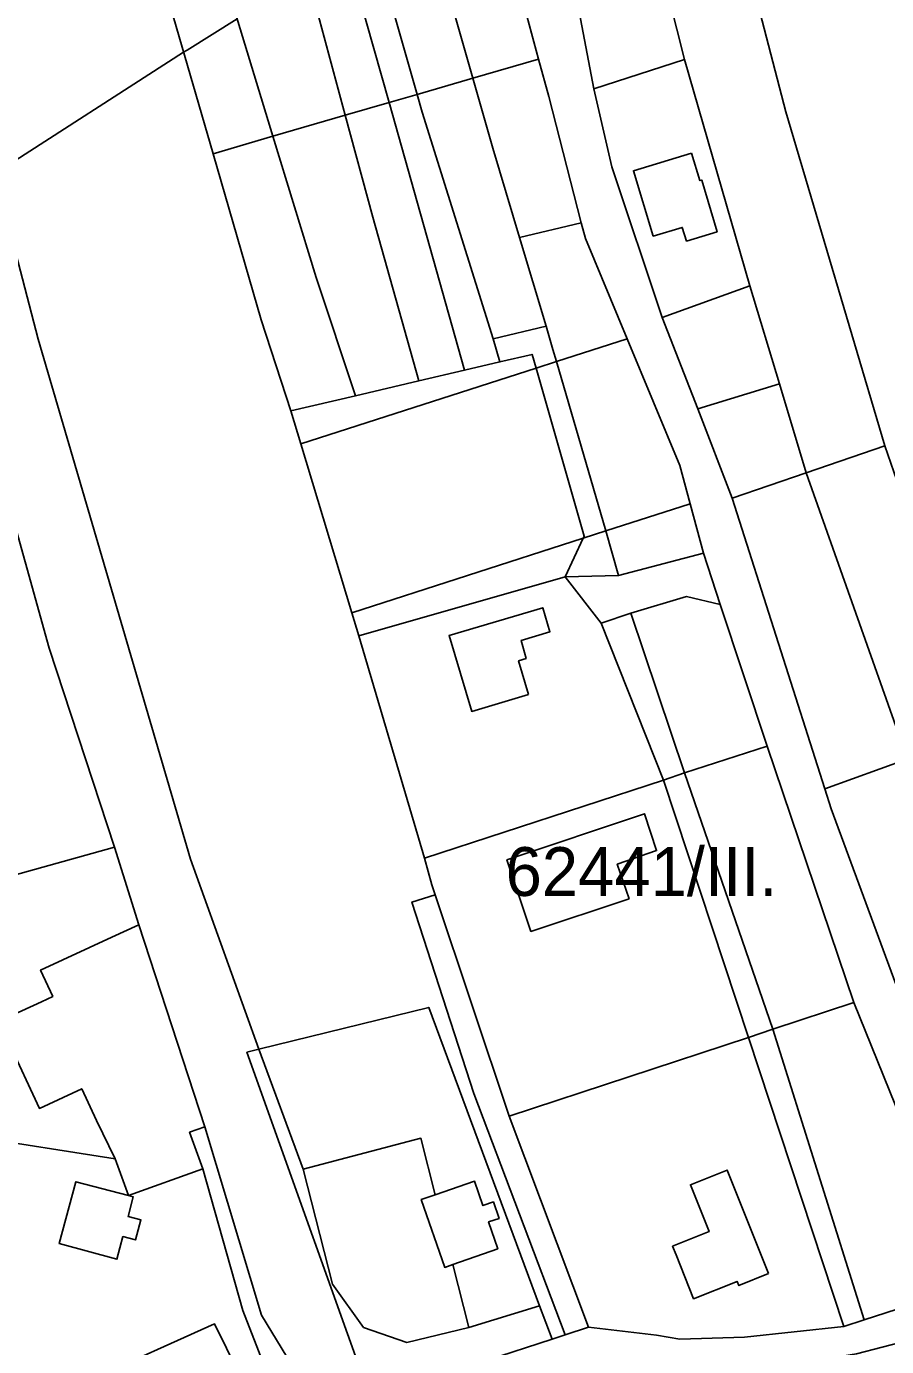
# Model space of a CAD drawing. Extents: x -502026 to -497664, y -1143484 to -1138019.
# Drawn here: x -498561.6 to -498420.5, y -1140148 to -1139931.4 of the extents above; entities that cross this region are included whole.
import ezdxf

# ---------------------------------------------------------------- set-up
doc = ezdxf.new("R2010")
doc.units = 0
for name, color, linetype in [('25', 7, 'Continuous'), ('37', 7, 'Continuous'), ('55', 7, 'Continuous'), ('62', 7, 'Continuous'), ('7', 7, 'Continuous')]:
    doc.layers.add(name, color=color, linetype=linetype)

msp = doc.modelspace()

# ---------------------------------------------------------------- linework, layer by layer
at = {"layer": '25'}
for points in [[(-498453.65, -1139936.81), (-498468.54, -1139941.63), (-498475.72, -1139903.67), (-498464.75, -1139892.81)], [(-498477.58, -1139936.75), (-498488.38, -1139939.89), (-498498.49, -1139904.41), (-498487.19, -1139901.13)], [(-498502.13, -1139943.88), (-498509.3, -1139945.96), (-498518.9, -1139910.34), (-498512.15, -1139908.38)], [(-498509.3, -1139945.96), (-498521.17, -1139949.4), (-498531.92, -1139914.12), (-498518.9, -1139910.34)], [(-498521.17, -1139949.4), (-498531.01, -1139952.26), (-498541.29, -1139916.84), (-498531.92, -1139914.12)], [(-498470.57, -1139963.59), (-498480.71, -1139966), (-498485.12, -1139951.34), (-498488.38, -1139939.89), (-498477.58, -1139936.75), (-498475.92, -1139942.9)], [(-498497.25, -1139989.53), (-498507.61, -1139991.96), (-498514.11, -1139972.59), (-498521.17, -1139949.4), (-498509.3, -1139945.96), (-498504.76, -1139962.67)], [(-498489.75, -1139987.77), (-498497.25, -1139989.53), (-498504.76, -1139962.67), (-498509.3, -1139945.96), (-498502.13, -1139943.88)], [(-498507.61, -1139991.96), (-498518.25, -1139994.45), (-498523.1, -1139979.49), (-498531.01, -1139952.26), (-498521.17, -1139949.4), (-498514.11, -1139972.59)], [(-498463.07, -1139982.62), (-498474.67, -1139986.36), (-498475.24, -1139984.39), (-498476.33, -1139980.54), (-498480.71, -1139966), (-498470.57, -1139963.59), (-498469.91, -1139966.15)], [(-498452.72, -1140009.7), (-498466.57, -1140014.16), (-498474.67, -1139986.36), (-498463.07, -1139982.62), (-498454.43, -1140003.42)], [(-498450.51, -1140017.8), (-498464.45, -1140021.44), (-498466.57, -1140014.16), (-498452.72, -1140009.7)]]:
    msp.add_lwpolyline(points, close=True, dxfattribs=at)
for points in [[(-498567.4, -1140071.66), (-498547.17, -1140066.02), (-498543.21, -1140078.75), (-498547.64, -1140080.8), (-498559.32, -1140086.21), (-498557.32, -1140090.52), (-498559.18, -1140091.38), (-498565.61, -1140094.35)], [(-498564.56, -1140097.96), (-498559.5, -1140108.89), (-498552.56, -1140105.68), (-498550.14, -1140110.9), (-498547.05, -1140117.17), (-498570.8, -1140113.45)]]:
    msp.add_lwpolyline(points, dxfattribs=at)
at = {"layer": '37'}
for points in [[(-498580.7, -1139904.91), (-498574.32, -1139926.66), (-498559.71, -1139982.7), (-498534.68, -1140067.99), (-498523.51, -1140099.19), (-498525.46, -1140099.67), (-498503.51, -1140161.05), (-498513.07, -1140159.27), (-498523.05, -1140142.79), (-498532.36, -1140111.9), (-498543.21, -1140078.75), (-498547.17, -1140066.02), (-498557.89, -1140033.39), (-498577.39, -1139963.52), (-498584.01, -1139942.13), (-498590.01, -1139920.48), (-498609.44, -1139845.64), (-498615.65, -1139814.41), (-498623.41, -1139785.38), (-498626.05, -1139772.41), (-498623.42, -1139762.03), (-498619.31, -1139757.84), (-498592.84, -1139833.58), (-498587.99, -1139880.06)], [(-498541.29, -1139916.84), (-498531.01, -1139952.26), (-498523.1, -1139979.49), (-498518.25, -1139994.45), (-498516.61, -1139999.88), (-498508.23, -1140027.57), (-498507.09, -1140031.35), (-498496.31, -1140067.84), (-498495.12, -1140072.22), (-498494.58, -1140073.83), (-498498.36, -1140075.04), (-498488.21, -1140106.42), (-498473.2, -1140146.05), (-498475.38, -1140146.76), (-498477.41, -1140141.29), (-498495.61, -1140092.32), (-498523.51, -1140099.19), (-498534.68, -1140067.99), (-498559.71, -1139982.7), (-498574.32, -1139926.66), (-498580.7, -1139904.91), (-498547.72, -1139894.69)], [(-498488.38, -1139939.89), (-498497.5, -1139942.53), (-498507.62, -1139907.06), (-498498.49, -1139904.41)], [(-498584.01, -1139942.13), (-498577.39, -1139963.52), (-498557.89, -1140033.39), (-498547.17, -1140066.02), (-498567.4, -1140071.66), (-498610.66, -1139931.23), (-498596.15, -1139928.3)], [(-498480.71, -1139966), (-498476.33, -1139980.54), (-498485.06, -1139982.65), (-498496.67, -1139945.43), (-498497.5, -1139942.53), (-498488.38, -1139939.89), (-498485.12, -1139951.34)], [(-498474.67, -1139986.36), (-498478, -1139987.43), (-498478.65, -1139985.18), (-498483.93, -1139986.41), (-498485.06, -1139982.65), (-498476.33, -1139980.54), (-498475.24, -1139984.39)], [(-498478, -1139987.43), (-498516.61, -1139999.88), (-498518.25, -1139994.45), (-498507.61, -1139991.96), (-498497.25, -1139989.53), (-498489.75, -1139987.77), (-498483.93, -1139986.41), (-498478.65, -1139985.18)], [(-498466.57, -1140014.16), (-498470.25, -1140015.35), (-498470.09, -1140015), (-498478, -1139987.43), (-498474.67, -1139986.36)], [(-498470.25, -1140015.35), (-498508.23, -1140027.57), (-498516.61, -1139999.88), (-498478, -1139987.43), (-498470.09, -1140015)], [(-498414.84, -1140017.25), (-498405.56, -1140044.31), (-498418.01, -1140048.78), (-498433.69, -1140004.63), (-498420.78, -1140000.2)], [(-498464.45, -1140021.44), (-498473.25, -1140021.69), (-498470.25, -1140015.35), (-498466.57, -1140014.16)], [(-498473.25, -1140021.69), (-498507.09, -1140031.35), (-498508.23, -1140027.57), (-498470.25, -1140015.35)], [(-498447.8, -1140026.22), (-498453.32, -1140024.92), (-498462.44, -1140027.62), (-498467.29, -1140029.26), (-498473.25, -1140021.69), (-498464.45, -1140021.44), (-498450.51, -1140017.8)], [(-498467.29, -1140029.26), (-498457.06, -1140055.04), (-498496.31, -1140067.84), (-498507.09, -1140031.35), (-498473.25, -1140021.69)], [(-498447.8, -1140026.22), (-498440.06, -1140049.48), (-498453.63, -1140053.81), (-498462.44, -1140027.62), (-498453.32, -1140024.92)], [(-498479.22, -1140040.97), (-498480.88, -1140035.47), (-498479.63, -1140035.09), (-498480.46, -1140032.1), (-498475.73, -1140030.7), (-498476.89, -1140026.75), (-498492.28, -1140031.32), (-498488.54, -1140043.77)], [(-498453.63, -1140053.81), (-498457.06, -1140055.04), (-498467.29, -1140029.26), (-498462.44, -1140027.62)], [(-498425.83, -1140091.5), (-498439.14, -1140095.88), (-498453.63, -1140053.81), (-498440.06, -1140049.48)], [(-498439.14, -1140095.88), (-498443.16, -1140097.25), (-498457.06, -1140055.04), (-498453.63, -1140053.81)], [(-498443.16, -1140097.25), (-498482.39, -1140110.14), (-498494.58, -1140073.83), (-498495.12, -1140072.22), (-498496.31, -1140067.84), (-498457.06, -1140055.04)], [(-498462.72, -1140074.51), (-498464.68, -1140068.83), (-498458.21, -1140066.6), (-498460.23, -1140060.56), (-498482.78, -1140068.12), (-498478.84, -1140079.86)], [(-498408.36, -1140134.77), (-498413.47, -1140140.15), (-498424.15, -1140143.6), (-498439.14, -1140095.88), (-498425.83, -1140091.5)], [(-498427.49, -1140144.66), (-498443.79, -1140146.41), (-498454.39, -1140146.74), (-498458.25, -1140146.09), (-498469.37, -1140144.8), (-498482.39, -1140110.14), (-498443.16, -1140097.25)], [(-498424.15, -1140143.6), (-498427.49, -1140144.66), (-498443.16, -1140097.25), (-498439.14, -1140095.88)], [(-498516.23, -1140118.88), (-498511.4, -1140137.73), (-498506.3, -1140144.84), (-498499.22, -1140147.29), (-498489.05, -1140144.84), (-498477.41, -1140141.29), (-498475.38, -1140146.76), (-498486.14, -1140150.27), (-498503.51, -1140161.05), (-498525.46, -1140099.67), (-498523.51, -1140099.19)], [(-498547.05, -1140117.17), (-498544.9, -1140123.19), (-498553.52, -1140120.93), (-498556.27, -1140131.07), (-498546.77, -1140133.65), (-498545.8, -1140129.93), (-498543.71, -1140130.48), (-498542.85, -1140127.18), (-498544.93, -1140126.63), (-498544.09, -1140123.4), (-498544.9, -1140123.19), (-498532.69, -1140118.83), (-498526.12, -1140142.06), (-498518.02, -1140162.88), (-498520.94, -1140164.17), (-498530.79, -1140144.21), (-498571.63, -1140162.6), (-498560.56, -1140182.88), (-498581.76, -1140187.79), (-498588.51, -1140166.89), (-498590.01, -1140162.02), (-498598.07, -1140136.66), (-498605.95, -1140115.74), (-498570.8, -1140113.45)], [(-498439.85, -1140136), (-498446.64, -1140119), (-498452.68, -1140121.42), (-498449.61, -1140129.11), (-498455.6, -1140131.51), (-498455.01, -1140132.92), (-498452.14, -1140140.13), (-498445, -1140137.27), (-498444.72, -1140137.97)], [(-498520.94, -1140164.17), (-498560.56, -1140182.88), (-498571.63, -1140162.6), (-498530.79, -1140144.21)]]:
    msp.add_lwpolyline(points, close=True, dxfattribs=at)
at = {"layer": '55'}
for points in [[(-498475.72, -1139903.67), (-498468.54, -1139941.63), (-498465.55, -1139954.43), (-498457.33, -1139979.14), (-498451.44, -1139994.1), (-498445.81, -1140008.75), (-498430.63, -1140056.46), (-498429.55, -1140059.73), (-498414.01, -1140101.85), (-498406.6, -1140113.23), (-498399.47, -1140125.86), (-498408.36, -1140134.77), (-498425.83, -1140091.5), (-498440.06, -1140049.48), (-498447.8, -1140026.22), (-498450.51, -1140017.8), (-498452.72, -1140009.7), (-498454.43, -1140003.42), (-498463.07, -1139982.62), (-498469.91, -1139966.15), (-498470.57, -1139963.59), (-498475.92, -1139942.9), (-498477.58, -1139936.75), (-498487.19, -1139901.13)], [(-498486.14, -1140150.27), (-498475.38, -1140146.76), (-498473.2, -1140146.05), (-498469.37, -1140144.8), (-498458.25, -1140146.09), (-498454.39, -1140146.74), (-498443.79, -1140146.41), (-498427.49, -1140144.66), (-498424.15, -1140143.6), (-498413.47, -1140140.15)], [(-498412.76, -1140145.86), (-498425.44, -1140149.16)]]:
    msp.add_lwpolyline(points, dxfattribs=at)
for points in [[(-498497.5, -1139942.53), (-498502.13, -1139943.88), (-498512.15, -1139908.38), (-498507.62, -1139907.06)], [(-498442.94, -1139973.93), (-498457.33, -1139979.14), (-498465.55, -1139954.43), (-498468.54, -1139941.63), (-498453.65, -1139936.81)], [(-498485.06, -1139982.65), (-498483.93, -1139986.41), (-498489.75, -1139987.77), (-498502.13, -1139943.88), (-498497.5, -1139942.53), (-498496.67, -1139945.43)], [(-498452.47, -1139952.17), (-498451.1, -1139956.68), (-498450.82, -1139956.59), (-498448.3, -1139965.07), (-498453.3, -1139966.6), (-498454.02, -1139964.35), (-498458.78, -1139965.77), (-498462.01, -1139955.06)], [(-498452.47, -1139952.17), (-498462.01, -1139955.06), (-498458.78, -1139965.77), (-498454.02, -1139964.35), (-498453.3, -1139966.6), (-498448.3, -1139965.07), (-498450.82, -1139956.59), (-498451.1, -1139956.68)], [(-498418.01, -1140048.78), (-498416.97, -1140051.55), (-498430.63, -1140056.46), (-498445.81, -1140008.75), (-498433.69, -1140004.63)], [(-498479.22, -1140040.97), (-498488.54, -1140043.77), (-498492.28, -1140031.32), (-498476.89, -1140026.75), (-498475.73, -1140030.7), (-498480.46, -1140032.1), (-498479.63, -1140035.09), (-498480.88, -1140035.47)], [(-498462.72, -1140074.51), (-498478.84, -1140079.86), (-498482.78, -1140068.12), (-498460.23, -1140060.56), (-498458.21, -1140066.6), (-498464.68, -1140068.83)], [(-498482.39, -1140110.14), (-498469.37, -1140144.8), (-498473.2, -1140146.05), (-498488.21, -1140106.42), (-498498.36, -1140075.04), (-498494.58, -1140073.83)], [(-498532.36, -1140111.9), (-498534.86, -1140112.8), (-498532.69, -1140118.83), (-498544.9, -1140123.19), (-498547.05, -1140117.17), (-498550.14, -1140110.9), (-498552.56, -1140105.68), (-498559.5, -1140108.89), (-498564.56, -1140097.96), (-498563.63, -1140097.35), (-498565.61, -1140094.35), (-498559.18, -1140091.38), (-498557.32, -1140090.52), (-498559.32, -1140086.21), (-498547.64, -1140080.8), (-498543.21, -1140078.75)], [(-498477.41, -1140141.29), (-498489.05, -1140144.84), (-498491.66, -1140134.51), (-498484.28, -1140131.93), (-498485.79, -1140127.52), (-498484.07, -1140126.93), (-498484.99, -1140124.24), (-498486.71, -1140124.83), (-498488.08, -1140120.84), (-498494.55, -1140123.06), (-498496.89, -1140113.78), (-498516.23, -1140118.88), (-498523.51, -1140099.19), (-498495.61, -1140092.32)], [(-498513.07, -1140159.27), (-498516.23, -1140162.11), (-498518.02, -1140162.88), (-498526.12, -1140142.06), (-498532.69, -1140118.83), (-498534.86, -1140112.8), (-498532.36, -1140111.9), (-498523.05, -1140142.79)], [(-498494.55, -1140123.06), (-498496.84, -1140123.84), (-498492.97, -1140134.97), (-498491.66, -1140134.51), (-498489.05, -1140144.84), (-498499.22, -1140147.29), (-498506.3, -1140144.84), (-498511.4, -1140137.73), (-498516.23, -1140118.88), (-498496.89, -1140113.78)], [(-498439.85, -1140136), (-498444.72, -1140137.97), (-498445, -1140137.27), (-498452.14, -1140140.13), (-498455.01, -1140132.92), (-498455.6, -1140131.51), (-498449.61, -1140129.11), (-498452.68, -1140121.42), (-498446.64, -1140119)], [(-498544.9, -1140123.19), (-498544.09, -1140123.4), (-498544.93, -1140126.63), (-498542.85, -1140127.18), (-498543.71, -1140130.48), (-498545.8, -1140129.93), (-498546.77, -1140133.65), (-498556.27, -1140131.07), (-498553.52, -1140120.93)], [(-498491.66, -1140134.51), (-498492.97, -1140134.97), (-498496.84, -1140123.84), (-498494.55, -1140123.06), (-498488.08, -1140120.84), (-498486.71, -1140124.83), (-498484.99, -1140124.24), (-498484.07, -1140126.93), (-498485.79, -1140127.52), (-498484.28, -1140131.93)], [(-498411.35, -1140148.65), (-498420.33, -1140152.76), (-498462.65, -1140162.35), (-498458.36, -1140154.39), (-498425.44, -1140149.16), (-498412.76, -1140145.86)]]:
    msp.add_lwpolyline(points, close=True, dxfattribs=at)
at = {"layer": '62'}
for points in [[(-498566.8, -1139955.49), (-498535.84, -1139935.62), (-498535.25, -1139935.25), (-498527.04, -1139930.15)], [(-498527.04, -1139930.15), (-498535.25, -1139935.25), (-498535.84, -1139935.62), (-498566.8, -1139955.49)]]:
    msp.add_lwpolyline(points, dxfattribs=at)
at = {"layer": '7'}
for points in [[(-498466.78, -1139830.91), (-498437.03, -1139945.38), (-498420.78, -1140000.2), (-498433.69, -1140004.63), (-498438.05, -1139990.01), (-498442.94, -1139973.93), (-498453.65, -1139936.81), (-498464.75, -1139892.81), (-498483.91, -1139827.39)], [(-498436.13, -1139851.5), (-498434.38, -1139865.1), (-498426.99, -1139890.99), (-498422.66, -1139906.15), (-498415.54, -1139939.75), (-498409.72, -1139960.93), (-498403.22, -1139983.81), (-498397.75, -1140003.05), (-498395.57, -1140010.69), (-498412.01, -1140016.27), (-498414.84, -1140017.25), (-498420.78, -1140000.2), (-498437.03, -1139945.38), (-498466.78, -1139830.91)], [(-498438.05, -1139990.01), (-498451.44, -1139994.1), (-498457.33, -1139979.14), (-498442.94, -1139973.93)], [(-498433.69, -1140004.63), (-498445.81, -1140008.75), (-498451.44, -1139994.1), (-498438.05, -1139990.01)], [(-498408.76, -1140072.76), (-498391.35, -1140117.72), (-498399.47, -1140125.86), (-498406.6, -1140113.23), (-498414.01, -1140101.85), (-498429.55, -1140059.73), (-498430.63, -1140056.46), (-498416.97, -1140051.55), (-498415.52, -1140055.3)]]:
    msp.add_lwpolyline(points, close=True, dxfattribs=at)

# ---------------------------------------------------------------- texts
at = {"layer": '62'}
msp.add_text('62441/III.', height=8, dxfattribs=at).set_placement((-498483, -1140074.03))

doc.saveas('drawing.dxf')
